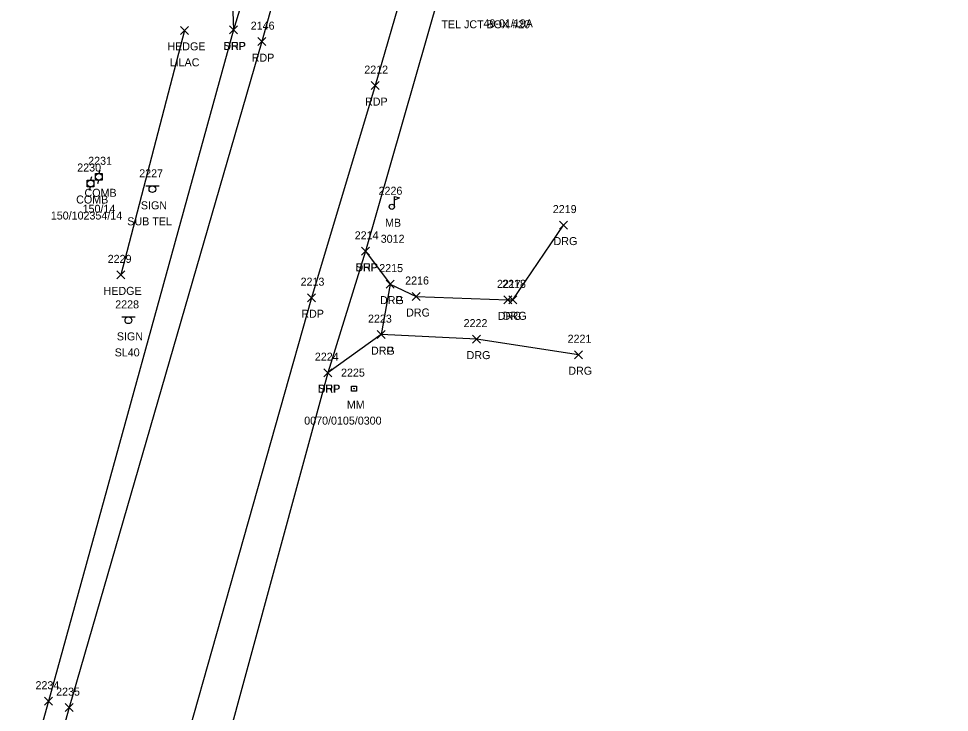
# Model space of a CAD drawing. Extents: x 1443071 to 1445292, y 614024 to 622563.
# Drawn here: x 1444521.8 to 1444754.4, y 621892.6 to 622066 of the extents above; entities that cross this region are included whole.
import ezdxf

# ---------------------------------------------------------------- set-up
doc = ezdxf.new("R2010")
doc.units = 0
for name, color, linetype in [('L_A', 7, 'Continuous'), ('L_C', 7, 'Continuous'), ('L_I', 7, 'Continuous'), ('L_TIC', 7, 'Continuous'), ('LAHR', 7, 'Continuous'), ('LMB', 7, 'Continuous'), ('P_A', 7, 'Continuous'), ('P_I', 7, 'Continuous'), ('P_TIC', 7, 'Continuous'), ('PET', 7, 'Continuous'), ('PSP', 7, 'Continuous'), ('R_A', 7, 'Continuous'), ('R_I', 7, 'Continuous'), ('R_TIC', 7, 'Continuous'), ('RDG', 7, 'Continuous'), ('RDP', 7, 'Continuous'), ('S_A', 7, 'Continuous'), ('S_C', 7, 'Continuous'), ('S_I', 7, 'Continuous'), ('SRM', 7, 'Continuous'), ('SSGN', 7, 'Continuous'), ('U_A', 7, 'Continuous'), ('U_C', 7, 'Continuous'), ('U_I', 7, 'Continuous'), ('UP', 7, 'Continuous')]:
    doc.layers.add(name, color=color, linetype=linetype)

msp = doc.modelspace()

# ---------------------------------------------------------------- linework, layer by layer
at = {"layer": 'L_TIC'}
for points in [[(1444562.28, 622062.06), (1444564.28, 622064.06)], [(1444564.28, 622062.06), (1444562.28, 622064.06)], [(1444546.33, 622000.95), (1444548.33, 622002.95)], [(1444548.33, 622000.95), (1444546.33, 622002.95)]]:
    msp.add_lwpolyline(points, dxfattribs=at)
at = {"layer": 'LAHR'}
msp.add_lwpolyline([(1444563.28, 622063.06), (1444547.33, 622001.95)], dxfattribs=at)
at = {"layer": 'LMB'}
for p, q in [((1444615.73, 622021.57), (1444617.02, 622021.18)), ((1444615.73, 622018.97), (1444615.73, 622021.57)), ((1444615.73, 622020.67), (1444617.01, 622021.18)), ((1444615.08, 622018.97), (1444615.08, 622018.97))]:
    msp.add_line(p, q, dxfattribs=at)
msp.add_circle((1444615.08, 622018.97), 0.656, dxfattribs=at)
at = {"layer": 'P_TIC'}
for points in [[(1444574.49, 622062.15), (1444576.49, 622064.15)], [(1444576.49, 622062.15), (1444574.49, 622064.15)], [(1444581.56, 622059.23), (1444583.56, 622061.23)], [(1444583.56, 622059.23), (1444581.56, 622061.23)], [(1444609.88, 622048.25), (1444611.88, 622050.25)], [(1444611.88, 622048.25), (1444609.88, 622050.25)], [(1444607.5, 622006.83), (1444609.5, 622008.83)], [(1444609.5, 622006.83), (1444607.5, 622008.83)], [(1444593.96, 621995.24), (1444595.96, 621997.24)], [(1444595.96, 621995.24), (1444593.96, 621997.24)], [(1444598.1, 621976.5), (1444600.1, 621978.5)], [(1444600.1, 621976.5), (1444598.1, 621978.5)], [(1444528.28, 621894.39), (1444530.28, 621896.39)], [(1444530.28, 621894.39), (1444528.28, 621896.39)], [(1444533.43, 621892.79), (1444535.43, 621894.79)], [(1444535.43, 621892.79), (1444533.43, 621894.79)]]:
    msp.add_lwpolyline(points, dxfattribs=at)
at = {"layer": 'PET'}
for points in [[(1444754.44, 622544.13), (1444741.07, 622497.37), (1444724.21, 622436.63), (1444710.62, 622388.87), (1444697.45, 622342.15), (1444675, 622264.13), (1444650.85, 622183.92), (1444630.28, 622116), (1444610.88, 622049.25), (1444594.96, 621996.24), (1444563.37, 621884.27), (1444533.4, 621779.05), (1444495.09, 621640.86), (1444437.04, 621433.18), (1444409.83, 621332.84), (1444393.99, 621275.61), (1444360.23, 621155.32)], [(1444707.59, 622509.11), (1444700.19, 622484.07), (1444679.05, 622409.28), (1444655.77, 622327.83), (1444650.07, 622306.66), (1444636.13, 622255.68), (1444623.55, 622208.8), (1444606.26, 622146.53), (1444595.29, 622106.04), (1444582.56, 622060.23), (1444534.43, 621893.79), (1444481.57, 621704.27), (1444439.29, 621553.82), (1444408.11, 621445.28), (1444395.03, 621397.39), (1444367.96, 621301.44), (1444350.41, 621238.76), (1444319.14, 621126.97)]]:
    msp.add_lwpolyline(points, dxfattribs=at)
at = {"layer": 'PSP'}
for points in [[(1444703.05, 622509.58), (1444696.35, 622485.04), (1444679.96, 622426.95), (1444670.67, 622398.4), (1444651.65, 622328.99), (1444645.77, 622309.01), (1444600.31, 622147.99), (1444589.19, 622108.06), (1444575.49, 622063.15), (1444529.28, 621895.39), (1444476.53, 621706.36), (1444455.46, 621630.82), (1444442.09, 621578.45), (1444424.77, 621519.75), (1444412.09, 621475.26), (1444390.88, 621397.93), (1444363.76, 621301.82), (1444345.99, 621239.2), (1444324.65, 621163.68)], [(1444745.15, 622495.54), (1444738.65, 622472.69), (1444728.21, 622436.2), (1444714.89, 622387.13), (1444701.45, 622339.69), (1444679.77, 622260.17), (1444671.12, 622229.57), (1444657.52, 622182.26), (1444644.19, 622133.53), (1444626.95, 622072.43), (1444608.5, 622007.83), (1444599.1, 621977.5), (1444572.99, 621881.76), (1444551.74, 621805.05), (1444541.41, 621769.53), (1444519.46, 621688.51), (1444505.68, 621638.77), (1444452.32, 621450.13), (1444441.68, 621411.27), (1444418.22, 621330.76), (1444405.98, 621283.95), (1444397.04, 621252.99), (1444383.69, 621203.04)]]:
    msp.add_lwpolyline(points, dxfattribs=at)
at = {"layer": 'R_TIC'}
for points in [[(1444574.49, 622062.15), (1444576.49, 622064.15)], [(1444576.49, 622062.15), (1444574.49, 622064.15)], [(1444657.02, 622013.39), (1444659.02, 622015.39)], [(1444659.02, 622013.39), (1444657.02, 622015.39)], [(1444607.5, 622006.83), (1444609.5, 622008.83)], [(1444609.5, 622006.83), (1444607.5, 622008.83)], [(1444613.62, 621998.64), (1444615.62, 622000.64)], [(1444615.62, 621998.64), (1444613.62, 622000.64)], [(1444613.62, 621998.64), (1444615.62, 622000.64)], [(1444615.62, 621998.64), (1444613.62, 622000.64)], [(1444620.16, 621995.54), (1444622.16, 621997.54)], [(1444622.16, 621995.54), (1444620.16, 621997.54)], [(1444643.05, 621994.7), (1444645.05, 621996.7)], [(1444645.05, 621994.7), (1444643.05, 621996.7)], [(1444644.35, 621994.71), (1444646.35, 621996.71)], [(1444646.35, 621994.71), (1444644.35, 621996.71)], [(1444611.38, 621986.01), (1444613.38, 621988.01)], [(1444613.38, 621986.01), (1444611.38, 621988.01)], [(1444611.38, 621986.01), (1444613.38, 621988.01)], [(1444613.38, 621986.01), (1444611.38, 621988.01)], [(1444635.28, 621984.89), (1444637.28, 621986.89)], [(1444637.28, 621984.89), (1444635.28, 621986.89)], [(1444660.7, 621980.99), (1444662.7, 621982.99)], [(1444662.7, 621980.99), (1444660.7, 621982.99)], [(1444598.1, 621976.5), (1444600.1, 621978.5)], [(1444600.1, 621976.5), (1444598.1, 621978.5)]]:
    msp.add_lwpolyline(points, dxfattribs=at)
at = {"layer": 'RDG'}
for points in [[(1444614.62, 621999.64), (1444621.16, 621996.54), (1444644.05, 621995.7), (1444645.35, 621995.71), (1444658.02, 622014.39)], [(1444661.7, 621981.99), (1444636.28, 621985.89), (1444612.38, 621987.01)]]:
    msp.add_lwpolyline(points, dxfattribs=at)
at = {"layer": 'RDP'}
for points in [[(1444645.77, 622309.01), (1444638.9, 622301.63), (1444626.44, 622256.61), (1444620.83, 622237.39), (1444614.71, 622214.93), (1444596.67, 622148.99), (1444585.03, 622109.27), (1444575.08, 622074.59), (1444575.49, 622063.15)], [(1444608.5, 622007.83), (1444614.62, 621999.64), (1444612.38, 621987.01), (1444599.1, 621977.5)]]:
    msp.add_lwpolyline(points, dxfattribs=at)
at = {"layer": 'SRM'}
msp.add_lwpolyline([(1444605.02, 621974.15), (1444606.27, 621974.15), (1444606.27, 621972.9), (1444605.02, 621972.9)], close=True, dxfattribs=at)
msp.add_circle((1444605.64, 621973.52), 0.0833, dxfattribs=at)
at = {"layer": 'SSGN'}
for p, q in [((1444553.57, 622024.18), (1444556.9, 622024.18)), ((1444555.22, 622023.35), (1444555.22, 622023.35)), ((1444547.57, 621991.43), (1444550.9, 621991.43)), ((1444549.22, 621990.59), (1444549.22, 621990.59))]:
    msp.add_line(p, q, dxfattribs=at)
for centre in [(1444555.22, 622023.35), (1444549.22, 621990.59)]:
    msp.add_circle(centre, 0.833, dxfattribs=at)
at = {"layer": 'UP'}
for p, q in [((1444542.12, 622028.12), (1444541.87, 622027.29)), ((1444538.96, 622023.94), (1444538.96, 622025.61)), ((1444538.96, 622025.61), (1444540.63, 622025.61)), ((1444540.05, 622026.44), (1444539.8, 622025.61)), ((1444540.63, 622025.61), (1444540.63, 622023.94)), ((1444541.04, 622025.62), (1444541.04, 622027.29)), ((1444541.04, 622027.29), (1444542.7, 622027.29)), ((1444542.7, 622025.62), (1444541.04, 622025.62)), ((1444541.62, 622024.79), (1444541.87, 622025.62)), ((1444541.87, 622026.46), (1444541.87, 622026.46)), ((1444542.7, 622027.29), (1444542.7, 622025.62)), ((1444540.63, 622023.94), (1444538.96, 622023.94)), ((1444539.55, 622023.11), (1444539.8, 622023.94)), ((1444539.8, 622024.78), (1444539.8, 622024.78))]:
    msp.add_line(p, q, dxfattribs=at)
for centre in [(1444539.8, 622024.78), (1444541.87, 622026.46)]:
    msp.add_circle(centre, 0.833, dxfattribs=at)

# ---------------------------------------------------------------- texts
at = {"layer": 'L_A'}
for s, p in [('HEDGE', (1444558.98, 622058.06)), ('MB', (1444613.38, 622013.97)), ('HEDGE', (1444543.03, 621996.95))]:
    msp.add_text(s, height=2, dxfattribs=at).set_placement(p)
at = {"layer": 'L_C'}
for s, p in [('LILAC', (1444559.55, 622054.06)), ('3012', (1444612.3, 622009.97))]:
    msp.add_text(s, height=2, dxfattribs=at).set_placement(p)
at = {"layer": 'L_I'}
for s, p in [('2226', (1444611.76, 622021.97)), ('2229', (1444544.06, 622004.95))]:
    msp.add_text(s, height=2, dxfattribs=at).set_placement(p)
at = {"layer": 'P_A'}
for s, p in [('SHP', (1444573.02, 622058.15)), ('RDP', (1444580.05, 622055.23)), ('RDP', (1444608.37, 622044.25)), ('SHP', (1444606.03, 622002.83)), ('RDP', (1444592.45, 621991.24)), ('SHP', (1444596.64, 621972.5))]:
    msp.add_text(s, height=2, dxfattribs=at).set_placement(p)
at = {"layer": 'P_I'}
for s, p in [('2146', (1444579.81, 622063.23)), ('2212', (1444608.19, 622052.25)), ('2214', (1444605.8, 622010.83)), ('2213', (1444592.27, 621999.24)), ('2224', (1444595.84, 621980.5)), ('2234', (1444526.02, 621898.39)), ('2235', (1444531.17, 621896.79))]:
    msp.add_text(s, height=2, dxfattribs=at).set_placement(p)
at = {"layer": 'R_A'}
for s, p in [('DRP', (1444572.97, 622058.15)), ('DRG', (1444655.5, 622009.39)), ('DRP', (1444605.99, 622002.83)), ('DRG', (1444612.11, 621994.64)), ('DRP', (1444612.11, 621994.64)), ('DRG', (1444618.65, 621991.54)), ('DRG', (1444641.54, 621990.7)), ('DRG', (1444642.83, 621990.71)), ('DRG', (1444609.87, 621982.01)), ('DRP', (1444609.87, 621982.01)), ('DRG', (1444633.77, 621980.89)), ('DRG', (1444659.19, 621976.99)), ('DRP', (1444596.59, 621972.5))]:
    msp.add_text(s, height=2, dxfattribs=at).set_placement(p)
at = {"layer": 'R_I'}
for s, p in [('2219', (1444655.31, 622017.39)), ('2214', (1444605.8, 622010.83)), ('2215', (1444611.93, 622002.64)), ('2215', (1444611.93, 622002.64)), ('2216', (1444618.41, 621999.54)), ('2217', (1444641.36, 621998.7)), ('2218', (1444642.65, 621998.71)), ('2223', (1444609.12, 621990.01)), ('2223', (1444609.12, 621990.01)), ('2222', (1444633.02, 621988.89)), ('2221', (1444659.01, 621984.99)), ('2224', (1444595.84, 621980.5))]:
    msp.add_text(s, height=2, dxfattribs=at).set_placement(p)
at = {"layer": 'S_A'}
for s, p in [('SIGN', (1444552.35, 622018.33)), ('SIGN', (1444546.35, 621985.57)), ('MM', (1444603.83, 621968.52))]:
    msp.add_text(s, height=2, dxfattribs=at).set_placement(p)
at = {"layer": 'S_C'}
for s, p in [('SUB TEL', (1444548.96, 622014.33)), ('SL40', (1444545.8, 621981.57)), ('0070/0105/0300', (1444593.18, 621964.52))]:
    msp.add_text(s, height=2, dxfattribs=at).set_placement(p)
at = {"layer": 'S_I'}
for s, p in [('2227', (1444551.94, 622026.33)), ('2228', (1444545.94, 621993.57)), ('2225', (1444602.38, 621976.52))]:
    msp.add_text(s, height=2, dxfattribs=at).set_placement(p)
at = {"layer": 'U_A'}
for p in [(1444538.26, 622021.46), (1444536.18, 622019.78)]:
    msp.add_text('COMB', height=2, dxfattribs=at).set_placement(p)
at = {"layer": 'U_C'}
for s, p in [('TEL JCT BOX #20', (1444627.47, 622063.57)), ('49-01/19A', (1444637.98, 622063.81)), ('150/14', (1444537.79, 622017.46)), ('150/102354/14', (1444529.84, 622015.78))]:
    msp.add_text(s, height=2, dxfattribs=at).set_placement(p)
at = {"layer": 'U_I'}
for s, p in [('2231', (1444539.18, 622029.46)), ('2230', (1444536.45, 622027.78))]:
    msp.add_text(s, height=2, dxfattribs=at).set_placement(p)

doc.saveas('drawing.dxf')
